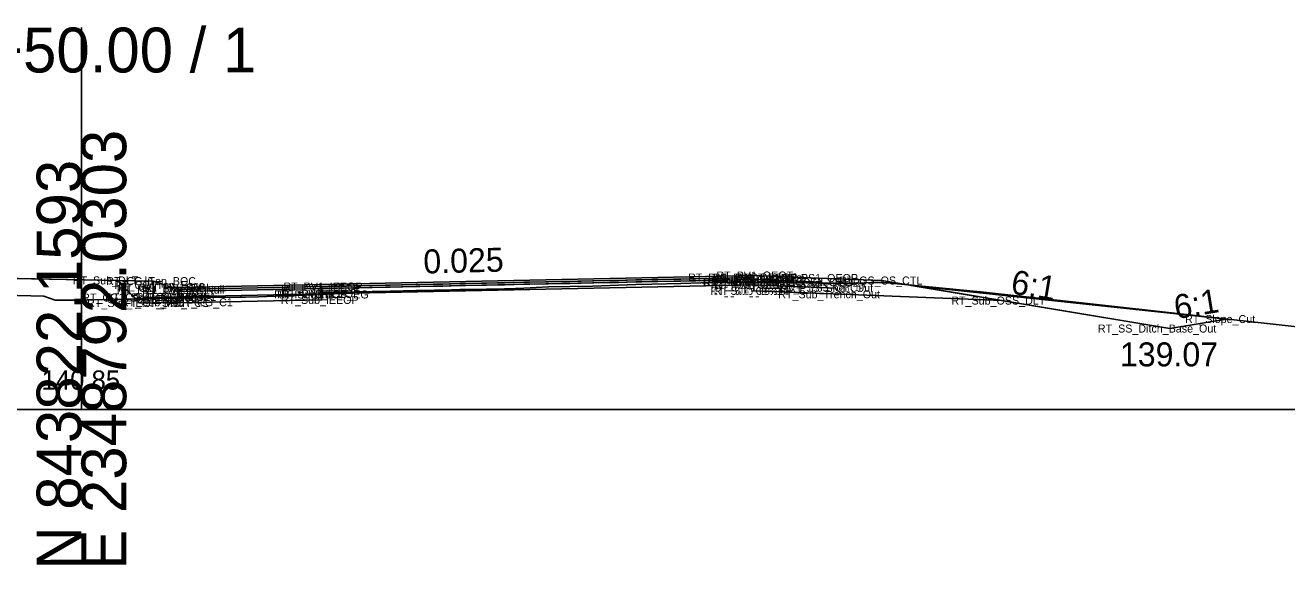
# Model space of a CAD drawing. Extents: x -26 to 2349090, y -10 to 844481.
# Drawn here: x 1146.5 to 1225.3, y 16990.3 to 17024 of the extents above; entities that cross this region are included whole.
import ezdxf

# ---------------------------------------------------------------- set-up
doc = ezdxf.new("R2010")
doc.units = 0
for name, color, linetype in [('Exist CMT Pavement', 7, 'Continuous'), ('Exist Cross Section Cell', 7, 'Continuous'), ('Exist XS Center Line Elevation Label', 7, 'Continuous'), ('Exist XS Ground Line', 7, 'Continuous'), ('Prop CMT Conc Surface', 7, 'Continuous'), ('Prop CMT Concrete Structures', 7, 'Continuous'), ('Prop CMT Pvmt Course 1', 7, 'Continuous'), ('Prop CMT Pvmt Course 1 CG', 7, 'Continuous'), ('Prop CMT Pvmt Course 1 Wedge', 7, 'Continuous'), ('Prop CMT Pvmt Course 2', 7, 'Continuous'), ('Prop CMT Pvmt Course 2 Wedge', 7, 'Continuous'), ('Prop CMT Pvmt Course 3', 7, 'Continuous'), ('Prop CMT Pvmt Course 3 Wedge', 7, 'Continuous'), ('Prop CMT Pvmt Surface', 7, 'Continuous'), ('Prop CMT Pvmt Surface Shoulder', 7, 'Continuous'), ('Prop CMT Pvmt Wedge Surface 1', 7, 'Continuous'), ('Prop CMT Pvmt Wedge Surface 2', 7, 'Continuous'), ('Prop CMT Pvmt Wedge Surface 3', 7, 'Continuous'), ('Prop CMT Shld Paved Course 1', 7, 'Continuous'), ('Prop CMT Shld Paved Course 2', 7, 'Continuous'), ('Prop CMT Shld Paved Course 3', 7, 'Continuous'), ('Prop CMT Slope Grass', 7, 'Continuous'), ('Prop CMT Subgrade Earthwork', 7, 'Continuous'), ('Prop Road Sect_ Recs - UUC (Outline)', 7, 'Continuous'), ('Prop Road Sect_ Recs - UUC (pattern)', 7, 'Continuous'), ('Prop XS Earthwork Shape', 7, 'Continuous'), ('Prop XS SE Text', 7, 'Continuous'), ('Prop XS Side Slope Text', 7, 'Continuous'), ('Scratch_Level_0', 7, 'Continuous')]:
    doc.layers.add(name, color=color, linetype=linetype)

msp = doc.modelspace()

# ---------------------------------------------------------------- linework, layer by layer
at = {"layer": 'Exist CMT Pavement'}
for p, q in [((1165.002, 17007.196), (1165.04, 17007.197)), ((1165.04, 17007.197), (1165.402, 17007.21)), ((1165.402, 17007.21), (1165.798, 17007.227)), ((1165.798, 17007.227), (1167.382, 17007.295)), ((1167.382, 17007.295), (1168.172, 17007.312)), ((1168.172, 17007.312), (1169.289, 17007.329)), ((1169.289, 17007.329), (1170.888, 17007.387)), ((1170.888, 17007.387), (1171.148, 17007.398)), ((1171.148, 17007.398), (1172.057, 17007.427)), ((1172.057, 17007.427), (1172.577, 17007.444)), ((1172.577, 17007.444), (1173.64, 17007.475)), ((1173.64, 17007.475), (1175.314, 17007.513)), ((1175.314, 17007.513), (1176.435, 17007.532)), ((1176.435, 17007.532), (1177.638, 17007.594)), ((1177.638, 17007.594), (1179.187, 17007.668)), ((1179.187, 17007.668), (1180.507, 17007.689)), ((1180.507, 17007.689), (1181.939, 17007.71)), ((1181.939, 17007.71), (1183.562, 17007.777)), ((1183.562, 17007.777), (1184.628, 17007.822)), ((1184.628, 17007.822), (1185.633, 17007.843)), ((1185.633, 17007.843), (1187.444, 17007.885)), ((1187.444, 17007.885), (1189.314, 17007.932)), ((1189.314, 17007.932), (1189.893, 17007.947)), ((1189.893, 17007.947), (1190.167, 17007.951)), ((1190.167, 17007.951), (1191.786, 17007.955)), ((1191.786, 17007.955), (1191.999, 17007.954))]:
    msp.add_line(p, q, dxfattribs=at)
at = {"layer": 'Exist Cross Section Cell'}
for p, q in [((1150, 17000), (1150, 17023.866)), ((1000, 17000), (1150, 17000)), ((1150, 17000), (1300, 17000))]:
    msp.add_line(p, q, dxfattribs=at)
at = {"layer": 'Exist XS Ground Line'}
msp.add_lwpolyline([(1141.871, 17007.236), (1147.653, 17007.085), (1148.365, 17006.841), (1149.041, 17006.837), (1150, 17006.848), (1151.605, 17006.87), (1152.325, 17006.883), (1153.897, 17006.927), (1154.386, 17006.941), (1154.811, 17006.947), (1157.132, 17006.991), (1157.966, 17006.999), (1159.93, 17007.02), (1160.248, 17007.027), (1161.071, 17007.052), (1162.65, 17007.099), (1165.04, 17007.197), (1165.402, 17007.21), (1165.798, 17007.227), (1167.382, 17007.295), (1168.172, 17007.312), (1169.289, 17007.329), (1171.148, 17007.398), (1172.057, 17007.427), (1172.577, 17007.444), (1173.64, 17007.475), (1175.314, 17007.513), (1176.435, 17007.532), (1177.638, 17007.594), (1179.187, 17007.668), (1180.507, 17007.689), (1181.939, 17007.71), (1183.562, 17007.777), (1184.628, 17007.822), (1185.633, 17007.843), (1187.444, 17007.885), (1189.314, 17007.932), (1190.168, 17007.951), (1191.786, 17007.955), (1192.992, 17007.946), (1193.729, 17007.94), (1195.25, 17007.927), (1195.775, 17007.923), (1196.288, 17007.91), (1196.951, 17007.905), (1198.509, 17007.91), (1199.319, 17007.933), (1200.13, 17007.938), (1206.356, 17007.329), (1207.106, 17007.253), (1212.299, 17006.695), (1226.888, 17005.062)], dxfattribs=at)
at = {"layer": 'Prop CMT Conc Surface'}
for p, q in [((1155.249, 17007.777), (1154.49, 17008.027)), ((1155.25, 17007.61), (1155.249, 17007.777)), ((1156, 17007.626), (1155.25, 17007.61))]:
    msp.add_line(p, q, dxfattribs=at)
at = {"layer": 'Prop CMT Concrete Structures'}
for p, q in [((1155.249, 17007.777), (1154.49, 17008.027)), ((1154.49, 17008.027), (1154.49, 17007.011)), ((1155.25, 17007.61), (1155.249, 17007.777)), ((1156, 17007.626), (1155.25, 17007.61)), ((1156, 17007.042), (1156, 17007.626)), ((1154.49, 17007.011), (1156, 17007.042))]:
    msp.add_line(p, q, dxfattribs=at)
at = {"layer": 'Prop CMT Pvmt Course 1'}
for p, q in [((1156, 17007.626), (1192, 17008.379)), ((1192, 17008.254), (1165, 17007.689)), ((1192, 17008.379), (1192, 17008.129)), ((1192, 17008.129), (1192, 17008.254)), ((1192, 17008.129), (1192, 17008.129)), ((1156, 17007.376), (1156, 17007.626)), ((1165, 17007.564), (1156, 17007.376)), ((1165, 17007.689), (1165, 17007.564))]:
    msp.add_line(p, q, dxfattribs=at)
at = {"layer": 'Prop CMT Pvmt Course 1 CG'}
for p, q in [((1153.99, 17007), (1153.65, 17006.66)), ((1153.65, 17006.66), (1156, 17006.709)), ((1156, 17007.042), (1153.99, 17007)), ((1156, 17006.709), (1156, 17007.042))]:
    msp.add_line(p, q, dxfattribs=at)
at = {"layer": 'Prop CMT Pvmt Course 1 Wedge'}
for p, q in [((1177.638, 17007.953), (1179.187, 17007.986)), ((1179.187, 17007.986), (1180.507, 17008.013)), ((1180.507, 17008.013), (1181.939, 17008.043)), ((1181.939, 17008.043), (1183.562, 17008.077)), ((1183.562, 17008.077), (1184.628, 17008.099)), ((1184.628, 17007.974), (1183.562, 17007.952)), ((1184.628, 17008.099), (1185.633, 17008.12)), ((1185.633, 17007.995), (1184.628, 17007.974)), ((1185.633, 17008.12), (1187.444, 17008.158)), ((1187.444, 17008.033), (1185.633, 17007.995)), ((1187.444, 17008.158), (1189.314, 17008.197)), ((1189.314, 17008.072), (1187.444, 17008.033)), ((1189.314, 17008.197), (1189.893, 17008.209)), ((1189.893, 17008.084), (1189.314, 17008.072)), ((1189.893, 17008.209), (1190.167, 17008.215)), ((1190.167, 17008.09), (1189.893, 17008.084)), ((1190.167, 17008.215), (1191.786, 17008.249)), ((1191.786, 17008.124), (1190.167, 17008.09)), ((1191.786, 17008.249), (1192, 17008.254)), ((1192, 17008.129), (1191.786, 17008.124)), ((1192, 17008.254), (1192, 17008.129)), ((1165, 17007.689), (1165.04, 17007.69)), ((1165, 17007.564), (1165, 17007.689)), ((1165.04, 17007.565), (1165, 17007.564)), ((1165.04, 17007.69), (1165.402, 17007.697)), ((1165.402, 17007.572), (1165.04, 17007.565)), ((1165.402, 17007.697), (1165.798, 17007.705)), ((1165.798, 17007.58), (1165.402, 17007.572)), ((1165.798, 17007.705), (1167.382, 17007.739)), ((1167.382, 17007.614), (1165.798, 17007.58)), ((1167.382, 17007.739), (1168.172, 17007.755)), ((1168.172, 17007.63), (1167.382, 17007.614)), ((1168.172, 17007.755), (1169.289, 17007.778)), ((1169.289, 17007.653), (1168.172, 17007.63)), ((1169.289, 17007.778), (1170.888, 17007.812)), ((1170.888, 17007.687), (1169.289, 17007.653)), ((1170.888, 17007.812), (1171.148, 17007.817)), ((1171.148, 17007.692), (1170.888, 17007.687)), ((1171.148, 17007.817), (1172.057, 17007.836)), ((1172.057, 17007.711), (1171.148, 17007.692)), ((1172.057, 17007.836), (1172.577, 17007.847)), ((1172.577, 17007.722), (1172.057, 17007.711)), ((1172.577, 17007.847), (1173.64, 17007.87)), ((1173.64, 17007.745), (1172.577, 17007.722)), ((1173.64, 17007.87), (1175.314, 17007.905)), ((1175.314, 17007.78), (1173.64, 17007.745)), ((1175.314, 17007.905), (1176.435, 17007.928)), ((1176.435, 17007.803), (1175.314, 17007.78)), ((1176.435, 17007.928), (1177.638, 17007.953)), ((1177.638, 17007.828), (1176.435, 17007.803)), ((1179.187, 17007.861), (1177.638, 17007.828)), ((1180.507, 17007.888), (1179.187, 17007.861)), ((1181.939, 17007.918), (1180.507, 17007.888)), ((1183.562, 17007.952), (1181.939, 17007.918))]:
    msp.add_line(p, q, dxfattribs=at)
at = {"layer": 'Prop CMT Pvmt Course 2'}
for p, q in [((1192, 17007.795), (1192, 17008.129)), ((1192, 17008.129), (1192, 17008.129)), ((1192, 17008.129), (1192, 17007.795)), ((1156, 17007.376), (1165, 17007.564)), ((1156, 17007.042), (1156, 17007.376)), ((1165, 17007.23), (1156, 17007.042)), ((1165, 17007.564), (1165, 17007.23)), ((1192, 17007.795), (1192, 17007.795))]:
    msp.add_line(p, q, dxfattribs=at)
at = {"layer": 'Prop CMT Pvmt Course 2 Wedge'}
for p, q in [((1183.562, 17007.952), (1184.628, 17007.974)), ((1184.628, 17007.974), (1185.633, 17007.995)), ((1185.633, 17007.995), (1187.444, 17008.033)), ((1187.444, 17008.033), (1189.314, 17008.072)), ((1189.314, 17008.072), (1189.893, 17008.084)), ((1189.893, 17008.084), (1190.167, 17008.09)), ((1190.167, 17008.09), (1191.786, 17008.124)), ((1191.786, 17008.124), (1192, 17008.129)), ((1192, 17008.129), (1192, 17007.954)), ((1165, 17007.564), (1165.04, 17007.565)), ((1165, 17007.314), (1165, 17007.564)), ((1165.04, 17007.315), (1165, 17007.314)), ((1165.04, 17007.565), (1165.402, 17007.572)), ((1165.402, 17007.322), (1165.04, 17007.315)), ((1165.402, 17007.572), (1165.798, 17007.58)), ((1165.798, 17007.33), (1165.402, 17007.322)), ((1165.798, 17007.58), (1167.382, 17007.614)), ((1167.382, 17007.364), (1165.798, 17007.33)), ((1167.382, 17007.614), (1168.172, 17007.63)), ((1168.172, 17007.38), (1167.382, 17007.364)), ((1168.172, 17007.63), (1169.289, 17007.653)), ((1169.289, 17007.403), (1168.172, 17007.38)), ((1169.289, 17007.653), (1170.888, 17007.687)), ((1170.888, 17007.437), (1169.289, 17007.403)), ((1170.888, 17007.687), (1171.148, 17007.692)), ((1171.148, 17007.442), (1170.888, 17007.437)), ((1171.148, 17007.692), (1172.057, 17007.711)), ((1172.057, 17007.461), (1171.148, 17007.442)), ((1172.057, 17007.711), (1172.577, 17007.722)), ((1172.577, 17007.472), (1172.057, 17007.461)), ((1172.577, 17007.722), (1173.64, 17007.745)), ((1173.64, 17007.495), (1172.577, 17007.472)), ((1173.64, 17007.745), (1175.314, 17007.78)), ((1175.314, 17007.53), (1173.64, 17007.495)), ((1175.314, 17007.78), (1176.435, 17007.803)), ((1176.435, 17007.553), (1175.314, 17007.53)), ((1176.435, 17007.803), (1177.638, 17007.828)), ((1177.116, 17007.567), (1176.435, 17007.553)), ((1177.638, 17007.594), (1177.116, 17007.567)), ((1177.638, 17007.828), (1179.187, 17007.861)), ((1179.187, 17007.668), (1177.638, 17007.594)), ((1179.187, 17007.861), (1180.507, 17007.888)), ((1180.507, 17007.689), (1179.187, 17007.668)), ((1180.507, 17007.888), (1181.939, 17007.918)), ((1181.939, 17007.71), (1180.507, 17007.689)), ((1181.939, 17007.918), (1183.562, 17007.952)), ((1183.562, 17007.777), (1181.939, 17007.71)), ((1184.628, 17007.822), (1183.562, 17007.777)), ((1185.633, 17007.843), (1184.628, 17007.822)), ((1187.444, 17007.885), (1185.633, 17007.843)), ((1189.314, 17007.932), (1187.444, 17007.885)), ((1189.893, 17007.947), (1189.314, 17007.932)), ((1190.167, 17007.951), (1189.893, 17007.947)), ((1191.786, 17007.955), (1190.167, 17007.951)), ((1192, 17007.954), (1191.786, 17007.955))]:
    msp.add_line(p, q, dxfattribs=at)
at = {"layer": 'Prop CMT Pvmt Course 3'}
for p, q in [((1156, 17007.042), (1165, 17007.23)), ((1165, 17007.23), (1165, 17006.855)), ((1192, 17007.795), (1192, 17007.795)), ((1192, 17007.795), (1192, 17007.42)), ((1192, 17007.42), (1192, 17007.795)), ((1192, 17007.42), (1192, 17007.42)), ((1156, 17006.667), (1156, 17007.042)), ((1165, 17006.855), (1156, 17006.667))]:
    msp.add_line(p, q, dxfattribs=at)
at = {"layer": 'Prop CMT Pvmt Course 3 Wedge'}
for p, q in [((1165, 17007.23), (1165.04, 17007.231)), ((1165, 17007.196), (1165, 17007.23)), ((1165.04, 17007.197), (1165, 17007.196)), ((1165.04, 17007.231), (1165.402, 17007.239)), ((1165.402, 17007.21), (1165.04, 17007.197)), ((1165.402, 17007.239), (1165.798, 17007.247)), ((1165.798, 17007.227), (1165.402, 17007.21)), ((1165.798, 17007.247), (1166.717, 17007.266)), ((1166.717, 17007.266), (1165.798, 17007.227))]:
    msp.add_line(p, q, dxfattribs=at)
at = {"layer": 'Prop CMT Pvmt Surface'}
msp.add_line((1156, 17007.626), (1192, 17008.379), dxfattribs=at)
at = {"layer": 'Prop CMT Pvmt Surface Shoulder'}
msp.add_line((1192, 17008.379), (1196, 17008.222), dxfattribs=at)
at = {"layer": 'Prop CMT Pvmt Wedge Surface 1'}
for p, q in [((1165, 17007.689), (1192, 17008.254)), ((1192, 17008.254), (1192, 17008.379)), ((1192, 17008.254), (1192, 17008.254)), ((1156, 17007.501), (1165, 17007.689)), ((1156, 17007.626), (1156, 17007.501))]:
    msp.add_line(p, q, dxfattribs=at)
at = {"layer": 'Prop CMT Pvmt Wedge Surface 2'}
for p, q in [((1156, 17007.376), (1192, 17008.129)), ((1192, 17008.129), (1192, 17008.379)), ((1156, 17007.626), (1156, 17007.376))]:
    msp.add_line(p, q, dxfattribs=at)
at = {"layer": 'Prop CMT Pvmt Wedge Surface 3'}
for p, q in [((1192, 17007.795), (1192, 17008.379)), ((1156, 17007.042), (1192, 17007.795)), ((1156, 17007.626), (1156, 17007.042))]:
    msp.add_line(p, q, dxfattribs=at)
at = {"layer": 'Prop CMT Shld Paved Course 1'}
for p, q in [((1192, 17008.379), (1196, 17008.222)), ((1192, 17008.129), (1192, 17008.379)), ((1196.26, 17007.962), (1192, 17008.129)), ((1196, 17008.222), (1196.26, 17007.962))]:
    msp.add_line(p, q, dxfattribs=at)
at = {"layer": 'Prop CMT Shld Paved Course 2'}
for p, q in [((1192, 17008.129), (1196.26, 17007.962)), ((1192, 17007.795), (1192, 17008.129)), ((1196.607, 17007.615), (1192, 17007.795)), ((1196.26, 17007.962), (1196.607, 17007.615))]:
    msp.add_line(p, q, dxfattribs=at)
at = {"layer": 'Prop CMT Shld Paved Course 3'}
for p, q in [((1192, 17007.795), (1196.607, 17007.615)), ((1192, 17007.42), (1192, 17007.795)), ((1197.497, 17007.205), (1192, 17007.42)), ((1196.607, 17007.615), (1197.107, 17007.596)), ((1197.107, 17007.596), (1197.497, 17007.205))]:
    msp.add_line(p, q, dxfattribs=at)
at = {"layer": 'Prop CMT Slope Grass'}
for p, q in [((1154.49, 17008.027), (1144, 17008.236)), ((1196, 17008.222), (1200, 17008.066)), ((1200, 17008.066), (1218, 17005.066)), ((1218, 17005.066), (1221.552, 17005.659))]:
    msp.add_line(p, q, dxfattribs=at)
at = {"layer": 'Prop CMT Subgrade Earthwork'}
for p, q in [((1152.238, 17008.072), (1153.65, 17006.66)), ((1165, 17006.855), (1165.002, 17007.196)), ((1192, 17007.42), (1191.999, 17007.954)), ((1192, 17007.42), (1197.497, 17007.205)), ((1192, 17007.42), (1192, 17007.42)), ((1197.497, 17007.205), (1207.511, 17006.814)), ((1156, 17006.709), (1153.65, 17006.66)), ((1165, 17006.855), (1156, 17006.667)), ((1156, 17006.667), (1156, 17006.709))]:
    msp.add_line(p, q, dxfattribs=at)
at = {"layer": 'Prop Road Sect_ Recs - UUC (Outline)'}
msp.add_lwpolyline([(1201.84, 17007.759), (1218, 17005.066), (1221.552, 17005.659)], close=True, dxfattribs=at)
at = {"layer": 'Prop Road Sect_ Recs - UUC (pattern)'}
msp.add_lwpolyline([(1201.84, 17007.759), (1218, 17005.066), (1221.552, 17005.659), (1201.84, 17007.759)], dxfattribs=at)
at = {"layer": 'Prop XS Earthwork Shape'}
for points in [[(1149.041, 17006.837), (1150, 17006.848), (1151.605, 17006.87), (1152.325, 17006.883), (1153.396, 17006.913), (1152.238, 17008.072), (1144, 17008.236), (1135.653, 17007.882), (1135.177, 17007.405), (1141.871, 17007.236), (1147.653, 17007.085), (1148.365, 17006.841)], [(1153.396, 17006.913), (1153.897, 17006.927), (1154.386, 17006.941), (1154.811, 17006.947), (1157.132, 17006.991), (1157.966, 17006.999), (1159.93, 17007.02), (1160.248, 17007.027), (1161.071, 17007.052), (1162.65, 17007.099), (1165.002, 17007.196), (1165, 17006.855), (1156, 17006.667), (1156, 17006.709), (1153.65, 17006.66)], [(1169.289, 17007.329), (1170.888, 17007.387), (1171.148, 17007.398)], [(1189.314, 17007.932), (1189.893, 17007.947), (1190.167, 17007.951)], [(1195.775, 17007.923), (1196.288, 17007.91), (1196.951, 17007.905), (1198.509, 17007.91), (1199.319, 17007.933), (1200.13, 17007.938), (1201.671, 17007.787), (1207.511, 17006.814), (1197.497, 17007.205), (1192, 17007.42), (1191.999, 17007.954), (1192.992, 17007.946), (1193.729, 17007.94), (1195.25, 17007.927)], [(1201.671, 17007.787), (1206.356, 17007.329), (1207.106, 17007.253), (1212.299, 17006.695), (1221.552, 17005.659), (1218, 17005.066), (1207.511, 17006.814)]]:
    msp.add_lwpolyline(points, close=True, dxfattribs=at)

# ---------------------------------------------------------------- texts
at = {"layer": 'Exist Cross Section Cell'}
msp.add_text('51+50.00 / 1', height=2.8, dxfattribs=at).set_placement((1140, 17021.066))
for s, p in [('E 2348792.0303', (1152.8, 16990)), ('N 843822.1593', (1150, 16990))]:
    msp.add_text(s, height=2.8, rotation=90, dxfattribs=at).set_placement(p)
at = {"layer": 'Exist XS Center Line Elevation Label'}
msp.add_text('140.85', height=1.2, dxfattribs=at).set_placement((1147.506, 17001.248))
at = {"layer": 'Prop XS SE Text'}
msp.add_text('0.025', height=1.5, rotation=1.4321, dxfattribs=at).set_placement((1171.38, 17008.499))
msp.add_text('139.07', height=1.5, dxfattribs=at).set_placement((1214.883, 17002.702))
at = {"layer": 'Prop XS Side Slope Text'}
for rotation, p in [(350.53768, (1208.008, 17007.267)), (9.4809, (1218.398, 17005.643))]:
    msp.add_text('6:1', height=1.5, rotation=rotation, dxfattribs=at).set_placement(p)
at = {"layer": 'Scratch_Level_0'}
for s, p in [('RT_Sub_DLT_In', (1149.462, 17007.822)), ('RT_CG_Top_BOC', (1151.549, 17007.777)), ('RT_CG_Top_Face', (1152.052, 17007.527)), ('RT_PV1_OEOT_Overlay', (1187.898, 17008.004)), ('RT_Sub Tie Out', (1188.821, 17007.704)), ('RT_PV_OEEOP_EG', (1188.873, 17007.704)), ('RT_PV2_OEEOP', (1189.315, 17007.879)), ('RT_PV3_OEEOP', (1189.315, 17007.545)), ('RT_PV1_OEEOP', (1189.457, 17008.004)), ('RT_PV2_OEOT', (1189.532, 17007.879)), ('RT_PV3_OEOT', (1189.532, 17007.545)), ('RT_PV1_OEOT', (1189.673, 17008.129)), ('RT_PS1_OEOP', (1193.689, 17007.972)), ('RT_PS2_OEOP', (1193.807, 17007.712)), ('RT_GS_OS_CTL', (1197.331, 17007.816)), ('RT_CG1_Shelf_In_Med', (1150.049, 17006.75)), ('RT_CG_Bot_BOC1', (1151.474, 17006.761)), ('RT_PV1_Overlay_Null', (1152.205, 17007.251)), ('RT_CG_Top_Gut', (1152.297, 17007.36)), ('RT_CG_Bot_IE1', (1153.394, 17006.792)), ('RT_PV2_PGL', (1153.791, 17007.126)), ('RT_PV3_PGL', (1153.791, 17006.792)), ('RT_PV1_PGL', (1153.933, 17007.376)), ('RT_PV_IEEOP_EG', (1162.037, 17006.946)), ('RT_Sub Tie In', (1162.23, 17006.946)), ('RT_PV2_IEEOP', (1162.476, 17007.314)), ('RT_PV3_IEEOP', (1162.476, 17006.98)), ('RT_PV1_IEEOP', (1162.618, 17007.439)), ('RT_Sub_OEEOP', (1189.291, 17007.17)), ('RT_Sub_OEOT', (1189.508, 17007.17)), ('RT_Sub_Trench_Out', (1193.537, 17006.955)), ('RT_PS3_Shelf_Out', (1193.591, 17007.346)), ('RT_PS3_OEOP', (1194.154, 17007.365)), ('RT_Sub_IEOP_Med', (1150.354, 17006.41)), ('RT_Sub_IEOT_CG_C1', (1152.469, 17006.459)), ('RT_Sub_PGL', (1153.768, 17006.417)), ('RT_Sub_IEEOP', (1162.453, 17006.605)), ('RT_Sub_OSS_DLT', (1204.35, 17006.564)), ('RT_Slope_Cut', (1218.95, 17005.409)), ('RT_SS_Ditch_Base_Out', (1213.508, 17004.816))]:
    msp.add_text(s, height=0.5, dxfattribs=at).set_placement(p)

doc.saveas('drawing.dxf')
